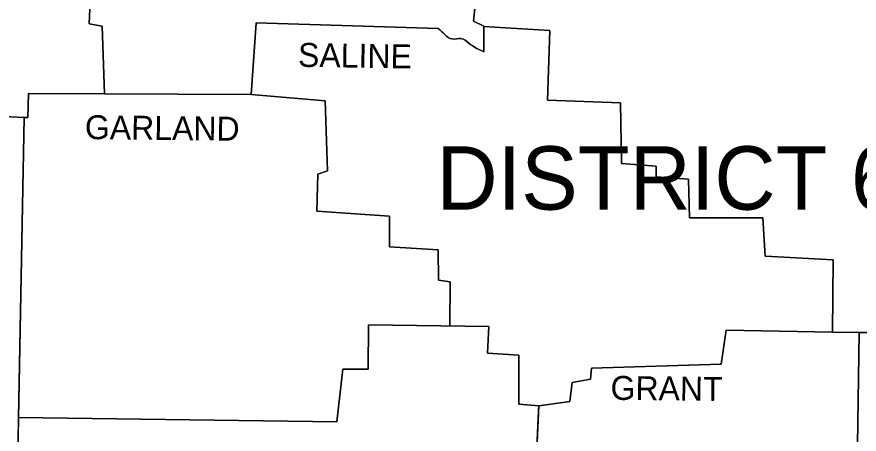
# Model space of a CAD drawing. Extents: x 185 to 5012, y 113 to 2127.
# Drawn here: x 2852.2 to 3000.3, y 1664.7 to 1738.2 of the extents above; entities that cross this region are included whole.
import ezdxf

# ---------------------------------------------------------------- set-up
doc = ezdxf.new("R2010")
doc.units = 0
doc.layers.add('Default', color=7, linetype='Continuous')
doc.layers.add('R_No Plot', color=7, linetype='Continuous')

msp = doc.modelspace()

# ---------------------------------------------------------------- linework, layer by layer
at = {"layer": 'Default'}
msp.add_line((2853.49, 1720.5), (2852.35, 1659.05), dxfattribs=at)
for points in [[(2965.22, 1751.12), (2958.18, 1751.9), (2958.47, 1749.26), (2945.66, 1748.77), (2945.26, 1744.96), (2933.23, 1744.27), (2932.54, 1737.42), (2934.31, 1736.54), (2934.31, 1732.04)], [(2865.03, 1739.58), (2864.94, 1736.93), (2867.19, 1736.54), (2867.6, 1724.64)], [(2926.28, 1736.15), (2894.29, 1737.13), (2893.41, 1724.51), (2854.27, 1724.7), (2854.11, 1720.47)], [(2934.31, 1736.49), (2945.95, 1735.76), (2945.56, 1723.53), (2958.37, 1723.04), (2958.57, 1712.38), (2964.64, 1711.89), (2964.64, 1710.03), (2970.31, 1709.64), (2970.51, 1702.79), (2983.42, 1702.79), (2983.81, 1696.04), (2995.75, 1695.45), (2995.65, 1682.71)], [(2893.41, 1724.51), (2906.42, 1723.43), (2906.81, 1711.1), (2905.15, 1710.52), (2904.95, 1703.96), (2917.77, 1703.08), (2917.77, 1697.7), (2926.28, 1697.21), (2926.38, 1691.83), (2928.44, 1691.53), (2928.33, 1683.8)], [(2853.49, 1720.5), (2815.14, 1721.96)], [(2854.11, 1720.47), (2853.49, 1720.5)], [(2852.51, 1667.66), (2908.48, 1666.88), (2909.55, 1676.17), (2913.96, 1676.17), (2914.05, 1684), (2935.19, 1683.71), (2934.99, 1679.01), (2940.47, 1678.62), (2940.47, 1670.01), (2943.99, 1669.72), (2943.95, 1668.82)], [(2943.99, 1669.72), (2949.47, 1670.5), (2949.86, 1673.83), (2953.09, 1674.41), (2953.29, 1676.37), (2976.08, 1677.05), (2976.96, 1683.02), (3000.35, 1682.63)], [(3000.35, 1682.63), (2999.76, 1642.91), (2997.51, 1642.81), (2997.22, 1618.25)], [(2943.99, 1669.72), (2942.82, 1644.08), (2941.94, 1644.37), (2942.03, 1631.18)]]:
    msp.add_lwpolyline(points, dxfattribs=at)
msp.add_spline([(2934.31, 1732.04), (2931.76, 1733.51), (2930.29, 1734.39), (2928.73, 1734.29), (2927.46, 1735.07), (2926.28, 1736.15)], degree=3, dxfattribs=at)
at = {"layer": 'R_No Plot'}
for p, q in [((2934.31, 1736.49), (2934.31, 1732.04)), ((2934.31, 1736.49), (2945.95, 1735.76)), ((2945.95, 1735.76), (2945.56, 1723.53)), ((2854.27, 1724.7), (2854.11, 1720.47)), ((2815.14, 1721.96), (2853.49, 1720.5)), ((2853.49, 1720.5), (2815.14, 1721.96)), ((2853.49, 1720.5), (2852.51, 1667.66)), ((2853.49, 1720.5), (2854.11, 1720.47)), ((2854.11, 1720.47), (2853.49, 1720.5)), ((2958.57, 1712.38), (2964.64, 1711.89)), ((2964.64, 1711.89), (2964.64, 1710.03)), ((2964.64, 1710.03), (2970.31, 1709.64)), ((2970.31, 1709.64), (2970.51, 1702.79)), ((2926.38, 1691.83), (2928.44, 1691.53)), ((2928.44, 1691.53), (2928.33, 1683.8)), ((2995.65, 1682.71), (3000.35, 1682.63)), ((3000.35, 1682.63), (3021.97, 1682.72)), ((2852.51, 1667.66), (2852.35, 1659.05))]:
    msp.add_line(p, q, dxfattribs=at)
for points in [[(2934.31, 1732.04), (2934.31, 1736.54), (2932.54, 1737.42), (2933.23, 1744.27), (2945.26, 1744.96), (2945.66, 1748.77), (2958.47, 1749.26), (2958.18, 1751.9), (2958.4, 1751.88)], [(2965.22, 1751.12), (2958.4, 1751.88), (2958.18, 1751.9), (2958.47, 1749.26), (2945.66, 1748.77), (2945.26, 1744.96), (2933.23, 1744.27), (2932.54, 1737.42), (2934.31, 1736.54), (2934.31, 1736.49)], [(2871.1, 1744.57), (2869.05, 1743.98), (2868.56, 1741.34), (2866.99, 1741.43), (2866.5, 1740.06), (2865.03, 1739.58), (2864.94, 1736.93)], [(2867.6, 1724.64), (2867.19, 1736.54), (2864.94, 1736.93), (2865.03, 1739.58)], [(2864.94, 1736.93), (2867.19, 1736.54), (2867.6, 1724.64)], [(2867.6, 1724.64), (2893.41, 1724.51), (2894.29, 1737.13), (2926.28, 1736.15)], [(2926.28, 1736.15), (2894.29, 1737.13), (2893.41, 1724.51)], [(2995.65, 1682.71), (2995.75, 1695.45), (2983.81, 1696.04), (2983.42, 1702.79), (2970.51, 1702.79), (2970.31, 1709.64), (2964.64, 1710.03), (2964.64, 1711.89), (2958.57, 1712.38), (2958.37, 1723.04), (2945.56, 1723.53), (2945.95, 1735.76), (2934.31, 1736.49)], [(2854.11, 1720.47), (2854.27, 1724.7), (2867.6, 1724.64)], [(2893.41, 1724.51), (2867.6, 1724.64), (2854.27, 1724.7)], [(2928.33, 1683.8), (2928.44, 1691.53), (2926.38, 1691.83), (2926.28, 1697.21), (2917.77, 1697.7), (2917.77, 1703.08), (2904.95, 1703.96), (2905.15, 1710.52), (2906.81, 1711.1), (2906.42, 1723.43), (2893.41, 1724.51)], [(2893.41, 1724.51), (2906.42, 1723.43), (2906.81, 1711.1)], [(2945.56, 1723.53), (2958.37, 1723.04), (2958.57, 1712.38)], [(2852.35, 1659.05), (2852.51, 1667.66), (2853.49, 1720.5)], [(2906.81, 1711.1), (2905.15, 1710.52), (2904.95, 1703.96), (2917.77, 1703.08)], [(2917.77, 1703.08), (2917.77, 1697.7), (2926.28, 1697.21), (2926.38, 1691.83)], [(2970.51, 1702.79), (2983.42, 1702.79), (2983.81, 1696.04)], [(2983.81, 1696.04), (2995.75, 1695.45), (2995.65, 1682.71)], [(2943.99, 1669.72), (2940.47, 1670.01), (2940.47, 1678.62), (2934.99, 1679.01), (2935.19, 1683.71), (2914.05, 1684), (2913.96, 1676.17), (2909.55, 1676.17), (2908.48, 1666.88), (2852.51, 1667.66)], [(2852.51, 1667.66), (2908.48, 1666.88), (2909.55, 1676.17), (2913.96, 1676.17), (2914.05, 1684), (2928.33, 1683.8)], [(2928.33, 1683.8), (2935.19, 1683.71), (2934.99, 1679.01), (2940.47, 1678.62), (2940.47, 1670.01), (2943.99, 1669.72)], [(3000.35, 1682.63), (2995.65, 1682.71), (2976.96, 1683.02), (2976.08, 1677.05), (2953.29, 1676.37), (2953.09, 1674.41), (2949.86, 1673.83), (2949.47, 1670.5), (2943.99, 1669.72)], [(2943.99, 1669.72), (2949.47, 1670.5), (2949.86, 1673.83), (2953.09, 1674.41), (2953.29, 1676.37), (2976.08, 1677.05), (2976.96, 1683.02), (2995.65, 1682.71)], [(2997.22, 1618.25), (2997.51, 1642.81), (2999.76, 1642.91), (3000.35, 1682.63)], [(3000.35, 1682.63), (2999.76, 1642.91), (2997.51, 1642.81)], [(3062.41, 1682.87), (3021.97, 1682.72), (3000.35, 1682.63)], [(2943.99, 1669.72), (2943.95, 1668.82), (2942.82, 1644.08), (2941.94, 1644.37), (2942.03, 1631.18)], [(2941.94, 1644.37), (2942.82, 1644.08), (2943.95, 1668.82), (2943.99, 1669.72)], [(2852.51, 1667.66), (2852.51, 1667.66)]]:
    msp.add_lwpolyline(points, dxfattribs=at)
for points in [[(2926.28, 1736.15), (2927.46, 1735.07), (2928.73, 1734.29), (2930.29, 1734.39), (2931.76, 1733.51), (2934.31, 1732.04)], [(2934.31, 1732.04), (2931.76, 1733.51), (2930.29, 1734.39), (2928.73, 1734.29), (2927.46, 1735.07), (2926.28, 1736.15)]]:
    msp.add_spline(points, degree=3, dxfattribs=at)

# ---------------------------------------------------------------- texts
at = {"layer": 'Default'}
for s, rotation, p in [('SALINE', 359.1491, (2901.63, 1729.4)), ('GARLAND', 359.3657, (2864.15, 1716.68)), ('GRANT', 359.4032, (2956.61, 1670.79))]:
    msp.add_text(s, height=4.208, rotation=rotation, dxfattribs=at).set_placement(p)
msp.add_text('DISTRICT 6', height=11.154, dxfattribs=at).set_placement((2925.99, 1704.25))

doc.saveas('drawing.dxf')
